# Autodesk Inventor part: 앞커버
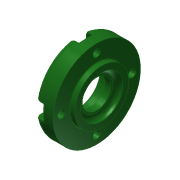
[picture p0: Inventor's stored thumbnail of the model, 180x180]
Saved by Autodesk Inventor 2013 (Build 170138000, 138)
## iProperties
Created: 2015-11
Part Number: 앞커버
Material: 알루미늄 6061
Document SubType Name: Modeling
Designer: mduedu
Density: 1 g/cm^3
Author: mduedu
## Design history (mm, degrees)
sketch "스케치1"
  geometry: L1 (-7, 0)-(7, 0); L2 (-7, 0)-(-7, 26); L3 (-7, 26)-(4, 26); L4 (4, 26)-(4, 16); L5 (4, 16)-(7, 16); L6 (7, 16)-(7, 0); 2 further points
  constraints: 12 end point, 3 perpendicular, 2 parallel, 1 coincident, 1 horizontal, 1 midpoint
  dimensions: "d0" = 14 distance of L1.start L1.end; "d1" = 52 diameter of L3 L1; "d2" = 3 distance of L4.end L5.end; "d3" = 32 diameter of L5 L1
revolve "회전1" sketch "스케치1" stored, may be unused: angle "d4" = 90 deg
hole "구멍1" diameter "d7" = 25; stored, may be unused: countersink angle "d11" = 90 deg, drill point angle "d13" = 0 deg; dims "d5" = 10, "d6" = 10, "d8" = 6, "d9" = 4, "d10" = 2, "d12" = 3
hole "구멍2" diameter "d16" = 25; stored, may be unused: countersink angle "d20" = 90 deg, drill point angle "d22" = 0 deg; dims "d17" = 6, "d18" = 4, "d19" = 2, "d21" = 7.3, "d62" = 10, "d63" = 10
hole "구멍3" diameter "d25" = 17; stored, may be unused: countersink angle "d29" = 90 deg, drill point angle "d31" = 0 deg; dims "d23" = 10, "d24" = 10, "d26" = 6, "d27" = 4, "d28" = 2, "d30" = 4.2
chamfer "모따기1" distance "d32" = 0.7; stored, may be unused: second distance "d33" = 2, angle "d34" = 30 deg
fillet "모깎기1" dims "d35" = 0.3
fillet "모깎기2" dims "d36" = 3
fillet "모깎기3" dims "d37" = 3
fillet "모깎기4" dims "d38" = 0.3
sketch "스케치3" dims "d61" = 42
  geometry: C1 r 26 at (0, 0) reference; 2 further points
  constraints: 2 vertical alignment, 1 coincident, 2 other
hole "구멍4" sketch "스케치3" at (0, -21) diameter "d44" = 4.5; stored, may be unused: countersink angle "d48" = 90 deg, drill point angle "d50" = 0 deg; dims "d45" = 6, "d46" = 8, "d47" = 4.6, "d49" = 8
sketch "스케치4"
  geometry: L1 (-4, 0)-(-4, -4.69); L2 (4, 0)-(4, -4.69); A1 r 4 centre (0, 0) between (3.614, -1.714) and (-3.614, -1.714) reference; A2 r 26 centre (0, 21) between (-4, -4.69) and (4, -4.69) reference; 1 further point
  constraints: 4 end point, 4 point on circle, 2 tangent, 1 parallel, 1 vertical
extrude "돌출1" cut sketch "스케치4" stored distance "d51" = 0; taper "d52" = 0 deg
fillet "모깎기5" dims "d56" = 0.3
fillet "모깎기6" dims "d57" = 1
node "솔리드1"
pattern_circular "원형 패턴1" dims angle "d54" = 360 deg
